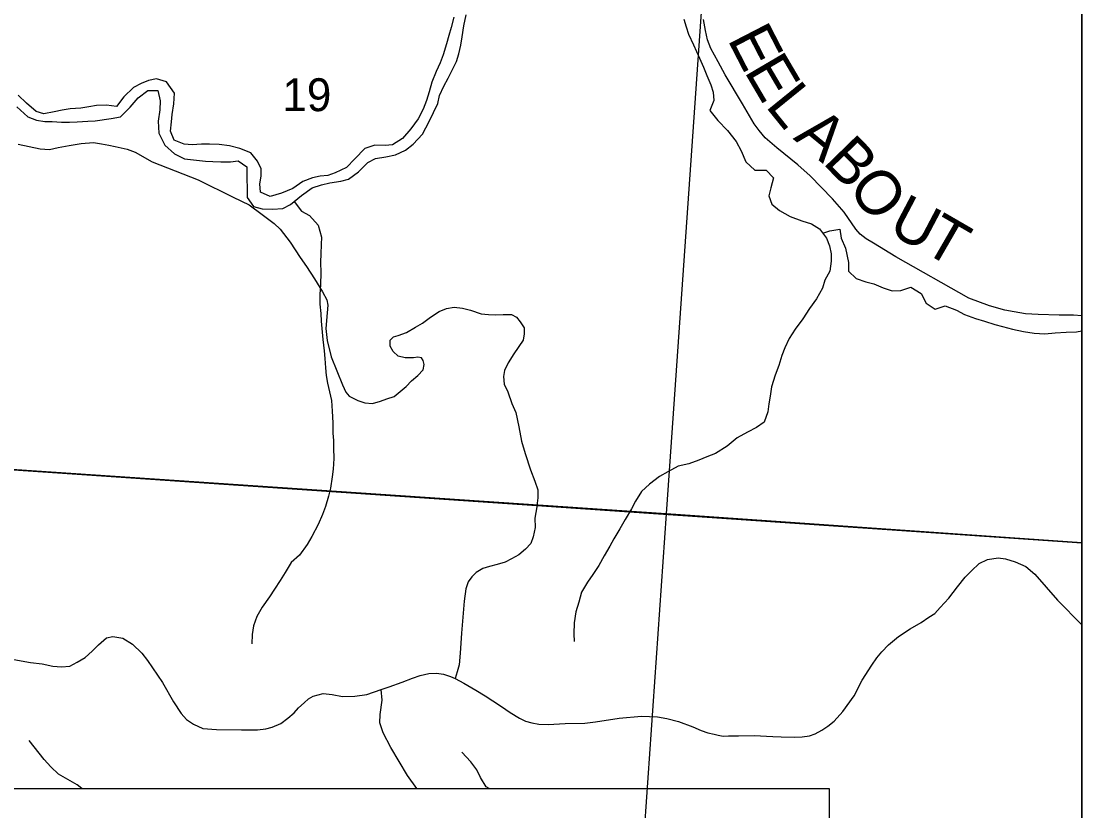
# Model space of a CAD drawing. Extents: x 0 to 34, y 0 to 22.
# Drawn here: x 7.55 to 8.9, y 18.398 to 19.403 of the extents above; entities that cross this region are included whole.
import ezdxf

# ---------------------------------------------------------------- set-up
doc = ezdxf.new("R2010")
doc.units = 0
for name, color, linetype in [('Default', 7, 'Continuous'), ('GM_X_County_Road', 7, 'Continuous'), ('GM_X_County_Road_Text', 7, 'Continuous'), ('GM_X_Major_River', 7, 'Continuous'), ('GM_X_Minor_River', 7, 'Continuous'), ('GM_X_Section', 7, 'Continuous'), ('GM_X_Section_Text', 7, 'Continuous'), ('GM_X_Township_Road', 7, 'Continuous'), ('SC_Scratch1', 7, 'Continuous'), ('SH_Data', 7, 'Continuous'), ('SH_Text', 7, 'Continuous')]:
    doc.layers.add(name, color=color, linetype=linetype)

msp = doc.modelspace()

# ---------------------------------------------------------------- linework, layer by layer
at = {"layer": 'Default'}
for points in [[(8.9, 18.739), (8.9, 19.7676), (8.4423, 19.798), (8.3709, 18.7757)], [(8.9, 17.7203), (8.9, 18.739), (8.3709, 18.7757), (8.3007, 17.7677)]]:
    msp.add_lwpolyline(points, close=True, dxfattribs=at)
at = {"layer": 'GM_X_County_Road'}
msp.add_lwpolyline([(8.9, 19.0278), (8.8893, 19.0287), (8.871, 19.0285), (8.8446, 19.0295), (8.8282, 19.0302), (8.8137, 19.0327), (8.8019, 19.0349), (8.7827, 19.0407), (8.7563, 19.0503), (8.6634, 19.103), (8.6349, 19.1201), (8.6255, 19.1257), (8.618, 19.1316), (8.6124, 19.1382), (8.5974, 19.1596), (8.5828, 19.1767), (8.5541, 19.2061), (8.5384, 19.2201), (8.5119, 19.2417), (8.4971, 19.2542), (8.4891, 19.2638), (8.4828, 19.2722), (8.4682, 19.2976), (8.4459, 19.3347), (8.437, 19.3509), (8.4278, 19.3679), (8.4234, 19.3789), (8.421, 19.3911), (8.4184, 19.4049)], dxfattribs=at)
at = {"layer": 'GM_X_Major_River'}
for points in [[(7.5441, 19.2938), (7.5581, 19.2809), (7.5691, 19.2767), (7.5797, 19.2752), (7.5892, 19.2752), (7.601, 19.2744), (7.6112, 19.2744), (7.6211, 19.2748), (7.6344, 19.2755), (7.6439, 19.2759), (7.6644, 19.2789), (7.6761, 19.2812), (7.6886, 19.2933), (7.6985, 19.3051), (7.711, 19.3145), (7.7236, 19.3145), (7.7266, 19.3016), (7.7262, 19.2898), (7.7243, 19.2754), (7.7251, 19.2602), (7.7326, 19.245), (7.7448, 19.234), (7.7577, 19.2276), (7.7842, 19.2245), (7.7937, 19.2241), (7.804, 19.2237), (7.8161, 19.2237), (7.826, 19.2252), (7.837, 19.2176), (7.837, 19.202), (7.8373, 19.1903), (7.8373, 19.1785), (7.8457, 19.1671), (7.8567, 19.1641), (7.8696, 19.1637), (7.8828, 19.1644), (7.8927, 19.1697), (7.9064, 19.1811), (7.92, 19.1906), (7.9322, 19.1947), (7.9428, 19.197), (7.9568, 19.1993), (7.9663, 19.2019), (7.9792, 19.211), (7.991, 19.2228), (8.0009, 19.2281), (8.0138, 19.23), (8.0263, 19.2326), (8.0388, 19.2387), (8.0487, 19.2462), (8.0605, 19.2591), (8.0692, 19.2751), (8.0745, 19.2868), (8.0802, 19.2982), (8.0821, 19.3081), (8.0878, 19.3199), (8.0935, 19.3305), (8.0988, 19.3415), (8.1038, 19.3517), (8.1068, 19.3612), (8.1095, 19.3722), (8.111, 19.3828), (8.1133, 19.3969), (8.1163, 19.4109)], [(8.1004, 19.4079), (8.097, 19.3946), (8.0943, 19.3844), (8.0913, 19.3741)], [(8.0913, 19.3741), (8.0871, 19.3601), (8.0833, 19.3498), (8.078, 19.3388), (8.0726, 19.3252), (8.0692, 19.313), (8.0658, 19.302), (8.0616, 19.2907), (8.0552, 19.2785), (8.0457, 19.2656), (8.035, 19.2535), (8.0225, 19.2455), (8.013, 19.2448), (8.0001, 19.2452), (7.9872, 19.2406), (7.9743, 19.2277), (7.9641, 19.2167), (7.9496, 19.2099), (7.9402, 19.2065), (7.9303, 19.2054), (7.9208, 19.2035), (7.9083, 19.1986), (7.8954, 19.1898), (7.881, 19.1838), (7.8669, 19.1796), (7.8544, 19.1853), (7.8536, 19.1959), (7.8552, 19.2054), (7.8552, 19.2149), (7.8506, 19.2248), (7.8419, 19.2351), (7.8282, 19.2408), (7.815, 19.2442), (7.8017, 19.2457), (7.7895, 19.2465), (7.7793, 19.2465), (7.7675, 19.2454), (7.7573, 19.2465), (7.7444, 19.2515), (7.7399, 19.2629), (7.741, 19.2746), (7.7418, 19.2841), (7.744, 19.2978), (7.7448, 19.3111), (7.7346, 19.3255), (7.7221, 19.3293), (7.7118, 19.3274), (7.7023, 19.3237), (7.6928, 19.3183), (7.6803, 19.3066), (7.6712, 19.2941), (7.6583, 19.296), (7.6458, 19.2956), (7.6359, 19.2937), (7.6257, 19.2922), (7.612, 19.2911), (7.6018, 19.2896), (7.5919, 19.2873), (7.5786, 19.2847), (7.5687, 19.2877), (7.5566, 19.2984), (7.546, 19.3086)]]:
    msp.add_lwpolyline(points, dxfattribs=at)
at = {"layer": 'GM_X_Minor_River'}
for points in [[(8.3935, 19.4052), (8.3962, 19.3957), (8.3992, 19.3862), (8.4056, 19.3726), (8.4132, 19.3559), (8.4185, 19.3442), (8.4227, 19.3335), (8.4277, 19.3218), (8.4307, 19.3123), (8.4315, 19.3017), (8.4266, 19.2892), (8.4368, 19.2763), (8.4489, 19.2638), (8.4599, 19.2497), (8.4664, 19.238), (8.4725, 19.2236), (8.4838, 19.213), (8.4982, 19.2134), (8.5077, 19.2035), (8.5043, 19.1906), (8.5017, 19.1807), (8.5055, 19.1701), (8.5153, 19.1618), (8.5286, 19.1542), (8.5437, 19.1485), (8.5558, 19.1451), (8.5661, 19.1387), (8.5752, 19.1265), (8.579, 19.1167), (8.5809, 19.1068), (8.5809, 19.0973), (8.5794, 19.0848), (8.573, 19.0731), (8.5699, 19.0628), (8.5624, 19.0496), (8.5533, 19.037), (8.545, 19.0241), (8.5352, 19.0109), (8.5276, 18.9991), (8.5219, 18.987), (8.5182, 18.9775), (8.5144, 18.9646), (8.5095, 18.9521), (8.505, 18.9376), (8.5031, 18.9255), (8.5016, 18.916), (8.5001, 18.9058), (8.4955, 18.8925), (8.4857, 18.8857), (8.4744, 18.8796), (8.4611, 18.8724), (8.4486, 18.8621), (8.4335, 18.8527), (8.4225, 18.8485), (8.4123, 18.8443), (8.3998, 18.8394), (8.3862, 18.8363), (8.3729, 18.8291), (8.3623, 18.8234), (8.3498, 18.8135), (8.3393, 18.8041), (8.3317, 18.7919), (8.3268, 18.7821), (8.3188, 18.7684), (8.3117, 18.7566), (8.3041, 18.7441), (8.2992, 18.7346), (8.292, 18.7225), (8.2852, 18.71), (8.2776, 18.6986), (8.2708, 18.6887)], [(7.8971, 19.1733), (7.9068, 19.1611), (7.9167, 19.1554), (7.9277, 19.1433), (7.9322, 19.1281), (7.9318, 19.1187), (7.9311, 19.1069), (7.9307, 19.0959), (7.9311, 19.0826), (7.9308, 19.0678), (7.93, 19.055), (7.93, 19.0428), (7.9312, 19.0307), (7.9316, 19.0208), (7.9331, 19.0072), (7.9339, 18.9977), (7.9354, 18.9833), (7.9362, 18.9734), (7.9373, 18.9617), (7.9381, 18.9518), (7.9396, 18.9419), (7.9423, 18.9309), (7.9446, 18.9199), (7.9457, 18.9063), (7.9465, 18.8915), (7.9465, 18.8786), (7.9473, 18.8691), (7.9473, 18.8593), (7.9477, 18.8464), (7.9469, 18.8327), (7.9458, 18.8228), (7.9436, 18.8084), (7.9409, 18.7982), (7.9371, 18.7853), (7.9334, 18.7751), (7.9277, 18.7622), (7.9198, 18.747), (7.9137, 18.7367), (7.9039, 18.7231), (7.8933, 18.714), (7.8857, 18.7011), (7.8793, 18.6908), (7.8721, 18.6798), (7.8657, 18.67), (7.8566, 18.6571), (7.8498, 18.6453), (7.8457, 18.6332), (7.8438, 18.6222), (7.8434, 18.6104)], [(8.5702, 19.1332), (8.5793, 19.136), (8.5918, 19.1383), (8.5937, 19.1266), (8.599, 19.114), (8.6032, 19.0958), (8.6029, 19.0845), (8.6127, 19.0754), (8.6252, 19.0712), (8.6351, 19.0685), (8.6472, 19.0636), (8.6586, 19.0595), (8.6695, 19.0602), (8.6824, 19.0644), (8.6953, 19.0561), (8.7017, 19.0439), (8.7135, 19.0363), (8.726, 19.0405), (8.7404, 19.0352), (8.7506, 19.0295), (8.7646, 19.0242), (8.776, 19.0208), (8.7892, 19.0167), (8.7991, 19.0144), (8.812, 19.011), (8.826, 19.008), (8.8392, 19.0057), (8.8529, 19.0049), (8.8661, 19.0061), (8.8801, 19.0072), (8.8934, 19.0076), (8.9, 19.0086)], [(8.2708, 18.6887), (8.2629, 18.6762), (8.2595, 18.6633), (8.2557, 18.6512), (8.2539, 18.6371), (8.2535, 18.6231), (8.2539, 18.6132)], [(7.5789, 18.4631), (7.56, 18.4874)], [(8.1454, 18.426), (8.1416, 18.4285), (8.1344, 18.4402), (8.1299, 18.4501), (8.1223, 18.4603), (8.1109, 18.4725)], [(7.627, 18.426), (7.621, 18.4309), (7.6092, 18.4377), (7.5971, 18.4445), (7.5873, 18.4536), (7.5789, 18.4631)]]:
    msp.add_lwpolyline(points, dxfattribs=at)
at = {"layer": 'GM_X_Section'}
for points in [[(8.4423, 19.798), (8.3709, 18.7757), (7.3808, 18.8429), (7.462, 19.8663)], [(8.3709, 18.7757), (8.3007, 17.7677), (7.3065, 17.8168), (7.3808, 18.8429)]]:
    msp.add_lwpolyline(points, close=True, dxfattribs=at)
at = {"layer": 'GM_X_Township_Road'}
for points in [[(7.5457, 19.2462), (7.5738, 19.2403), (7.5858, 19.2395), (7.5966, 19.242), (7.6109, 19.2445), (7.6259, 19.2471), (7.6416, 19.2483), (7.6519, 19.2469), (7.6614, 19.245), (7.6695, 19.2435), (7.6845, 19.2401), (7.6949, 19.2361), (7.7166, 19.2236), (7.7749, 19.201), (7.8196, 19.179), (7.8399, 19.1689), (7.8564, 19.1569), (7.8716, 19.1453), (7.8794, 19.1383), (7.8921, 19.1214), (7.905, 19.1022), (7.9128, 19.0905), (7.9231, 19.0747), (7.9333, 19.0582), (7.9388, 19.0483), (7.9401, 19.0412), (7.9392, 19.0318), (7.9375, 19.0118), (7.9392, 18.9965), (7.9445, 18.9758), (7.9588, 18.9399), (7.9629, 18.9308), (7.9671, 18.9254), (7.9783, 18.9199), (7.9872, 18.9169), (7.9971, 18.9163), (8.007, 18.9192), (8.0152, 18.922), (8.0245, 18.9251), (8.0398, 18.9378), (8.0467, 18.945), (8.0547, 18.9518), (8.0613, 18.9592), (8.0626, 18.9657), (8.0613, 18.9708), (8.0592, 18.9742), (8.0547, 18.975), (8.049, 18.9744), (8.0387, 18.9744), (8.0296, 18.9765), (8.0231, 18.9824), (8.0195, 18.9894), (8.0195, 18.9968), (8.0237, 19.0012), (8.0296, 19.0027), (8.0402, 19.0067), (8.0516, 19.0132), (8.0606, 19.0183), (8.0708, 19.0261), (8.0818, 19.0335), (8.0913, 19.0373), (8.1008, 19.039), (8.1114, 19.0375), (8.1219, 19.035), (8.1354, 19.0303), (8.1445, 19.0293), (8.1536, 19.0291), (8.1635, 19.0295), (8.1739, 19.0293), (8.1802, 19.0259), (8.1851, 19.02), (8.1899, 19.0126), (8.1901, 19.005), (8.1887, 18.997), (8.1768, 18.9794), (8.1699, 18.9678), (8.1652, 18.9583), (8.1637, 18.9505), (8.1646, 18.941), (8.1692, 18.9311), (8.1745, 18.9163), (8.1796, 18.9049), (8.1832, 18.8864), (8.1866, 18.8683), (8.1912, 18.8527), (8.1982, 18.8318), (8.2035, 18.8172), (8.2073, 18.8062), (8.2073, 18.7963), (8.2063, 18.7858), (8.2062, 18.7845), (8.2035, 18.7701), (8.2039, 18.7583), (8.2016, 18.7467), (8.1984, 18.738), (8.1918, 18.7308), (8.1834, 18.7234), (8.1739, 18.7186), (8.1659, 18.7143), (8.1557, 18.7114), (8.1458, 18.7088), (8.1373, 18.7061), (8.1291, 18.7012), (8.1234, 18.6957), (8.1188, 18.6894), (8.1158, 18.6805), (8.1135, 18.6647), (8.1105, 18.6239), (8.1084, 18.5986), (8.1073, 18.5838), (8.1048, 18.5745), (8.1022, 18.5661)], [(7.5402, 18.5902), (7.5618, 18.5867), (7.5766, 18.5848), (7.5902, 18.5817), (7.6011, 18.5809), (7.6118, 18.5821), (7.6211, 18.5868), (7.6312, 18.5928), (7.64, 18.6009), (7.6481, 18.6089), (7.6583, 18.6179), (7.6664, 18.6198), (7.6793, 18.6175), (7.6915, 18.6097), (7.7032, 18.5986), (7.7104, 18.5893), (7.7298, 18.5613), (7.7435, 18.5365), (7.7536, 18.5216), (7.7604, 18.5142), (7.7693, 18.5079), (7.7812, 18.5027), (7.7983, 18.5011), (7.8302, 18.5007), (7.8507, 18.5009), (7.8612, 18.5021), (7.8693, 18.5041), (7.8802, 18.509), (7.8893, 18.5156), (7.8972, 18.5227), (7.9026, 18.529), (7.9099, 18.5352), (7.9156, 18.5402), (7.9215, 18.5439), (7.9341, 18.5471), (7.9458, 18.5459), (7.959, 18.5435), (7.9746, 18.5437), (7.9898, 18.5459), (8.0082, 18.5523), (8.0182, 18.5558), (8.0349, 18.5617), (8.0478, 18.5667), (8.0576, 18.5701), (8.0688, 18.5725), (8.0786, 18.5732), (8.0872, 18.5718), (8.0962, 18.5689), (8.1022, 18.5661), (8.1131, 18.5601), (8.1287, 18.5512), (8.1403, 18.5441), (8.1501, 18.5379), (8.1611, 18.5307), (8.1723, 18.5229), (8.184, 18.5159), (8.1916, 18.5121), (8.1997, 18.5097), (8.2086, 18.5081), (8.2205, 18.5078), (8.2422, 18.5088), (8.2675, 18.5095), (8.2811, 18.5112), (8.3109, 18.5157), (8.3395, 18.5183), (8.36, 18.5174), (8.3719, 18.5152), (8.3865, 18.5116), (8.4049, 18.5045), (8.4153, 18.5002), (8.4237, 18.4971), (8.4318, 18.4952), (8.437, 18.4942), (8.4435, 18.493), (8.4504, 18.4933), (8.463, 18.4933), (8.4831, 18.4935), (8.5067, 18.4926), (8.5172, 18.4921), (8.5339, 18.4916), (8.5441, 18.4921), (8.5532, 18.4933), (8.5604, 18.4957), (8.5692, 18.5004), (8.5766, 18.5057), (8.5849, 18.5119), (8.5957, 18.5243), (8.6102, 18.5441), (8.6206, 18.5639), (8.6326, 18.583), (8.6391, 18.5925), (8.6455, 18.6003), (8.6541, 18.6091), (8.6667, 18.6197), (8.6813, 18.6295), (8.6954, 18.6373), (8.7054, 18.6443), (8.7128, 18.649), (8.7199, 18.6567), (8.7307, 18.6684), (8.7416, 18.6827), (8.7516, 18.6953), (8.7595, 18.7034), (8.7695, 18.7127), (8.7798, 18.7177), (8.7934, 18.7196), (8.8027, 18.7184), (8.8153, 18.7149), (8.8287, 18.7089), (8.8401, 18.6991), (8.869, 18.6657), (8.9, 18.6345)], [(8.0534, 18.426), (8.0417, 18.4428), (8.0205, 18.4782), (8.0106, 18.4969), (8.0065, 18.5099), (8.0067, 18.5202), (8.0094, 18.5387), (8.0082, 18.5523)]]:
    msp.add_lwpolyline(points, dxfattribs=at)
at = {"layer": 'SC_Scratch1'}
for points in [[(8.9, 18.7389), (8.9, 20.9), (5.53, 20.9), (5.4955, 20.3864), (5.4469, 19.6641), (5.4089, 19.0989), (5.4007, 18.9779), (5.4885, 18.9719), (5.9889, 18.9377), (6.8273, 18.8804), (7.2159, 18.8539), (8.2061, 18.7863)], [(5.0535, 14.1), (8.9, 14.1), (8.9, 18.7389), (8.2061, 18.7863), (7.2159, 18.8539), (6.8273, 18.8804), (5.9889, 18.9377), (5.4885, 18.9719), (5.4007, 18.9779), (5.3662, 18.4999), (5.3506, 18.2846), (5.2869, 17.4026), (5.2761, 17.2534), (5.1794, 15.9156), (5.1049, 14.8414), (5.0814, 14.5016)]]:
    msp.add_lwpolyline(points, close=True, dxfattribs=at)
at = {"layer": 'SH_Data'}
msp.add_line((8.9, 20.9), (8.9, 14.1), dxfattribs=at)
at = {"layer": 'SH_Text'}
msp.add_lwpolyline([(8.5782, 18.186), (7.1921, 18.186), (7.1921, 18.426), (8.5782, 18.426)], close=True, dxfattribs=at)

# ---------------------------------------------------------------- texts
at = {"layer": 'GM_X_County_Road_Text'}
for s, rotation, p in [('E', 297.2963, (8.4483, 19.38)), ('E', 300.4335, (8.4694, 19.3393)), ('L', 309.0115, (8.4962, 19.295)), ('A', 320.4249, (8.5317, 19.2532)), ('B', 314.1996, (8.569, 19.2225)), ('O', 308.0021, (8.6005, 19.1903)), ('U', 332.2469, (8.6513, 19.1342)), ('T', 329.933, (8.695, 19.1112))]:
    msp.add_text(s, height=0.0568, rotation=rotation, dxfattribs=at).set_placement(p)
at = {"layer": 'GM_X_Section_Text'}
msp.add_text('19', height=0.04186, rotation=0, dxfattribs=at).set_placement((7.8823, 19.2883))

doc.saveas('drawing.dxf')
